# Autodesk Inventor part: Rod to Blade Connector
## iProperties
Shininess: 64.0
Length Units: 11272
Angle Units: 11279
Time Units: 11290
Mass Units: 11286
Length Display Precision: 3
Angle Display Precision: 2
Compacted: True
Part Number: Rod to Blade Connector
Document SubType Name: Modeling
Created: 2003-10
Designer: jpittman
Manufacturer: Standard
Standards Organization: Custom
Density: 0.0
Volumn: 0.0
Area: 0.0
PropertySet Name: Model Information
Control State: 0
Master: False
Checked Out: False
Author: jpittman
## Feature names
1. Extrusion1
2. Extrusion2
3. Hole1
4. Hole2
5. Fillet1
